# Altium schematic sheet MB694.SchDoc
size A4; Revision: A.1(PCB.SCH)
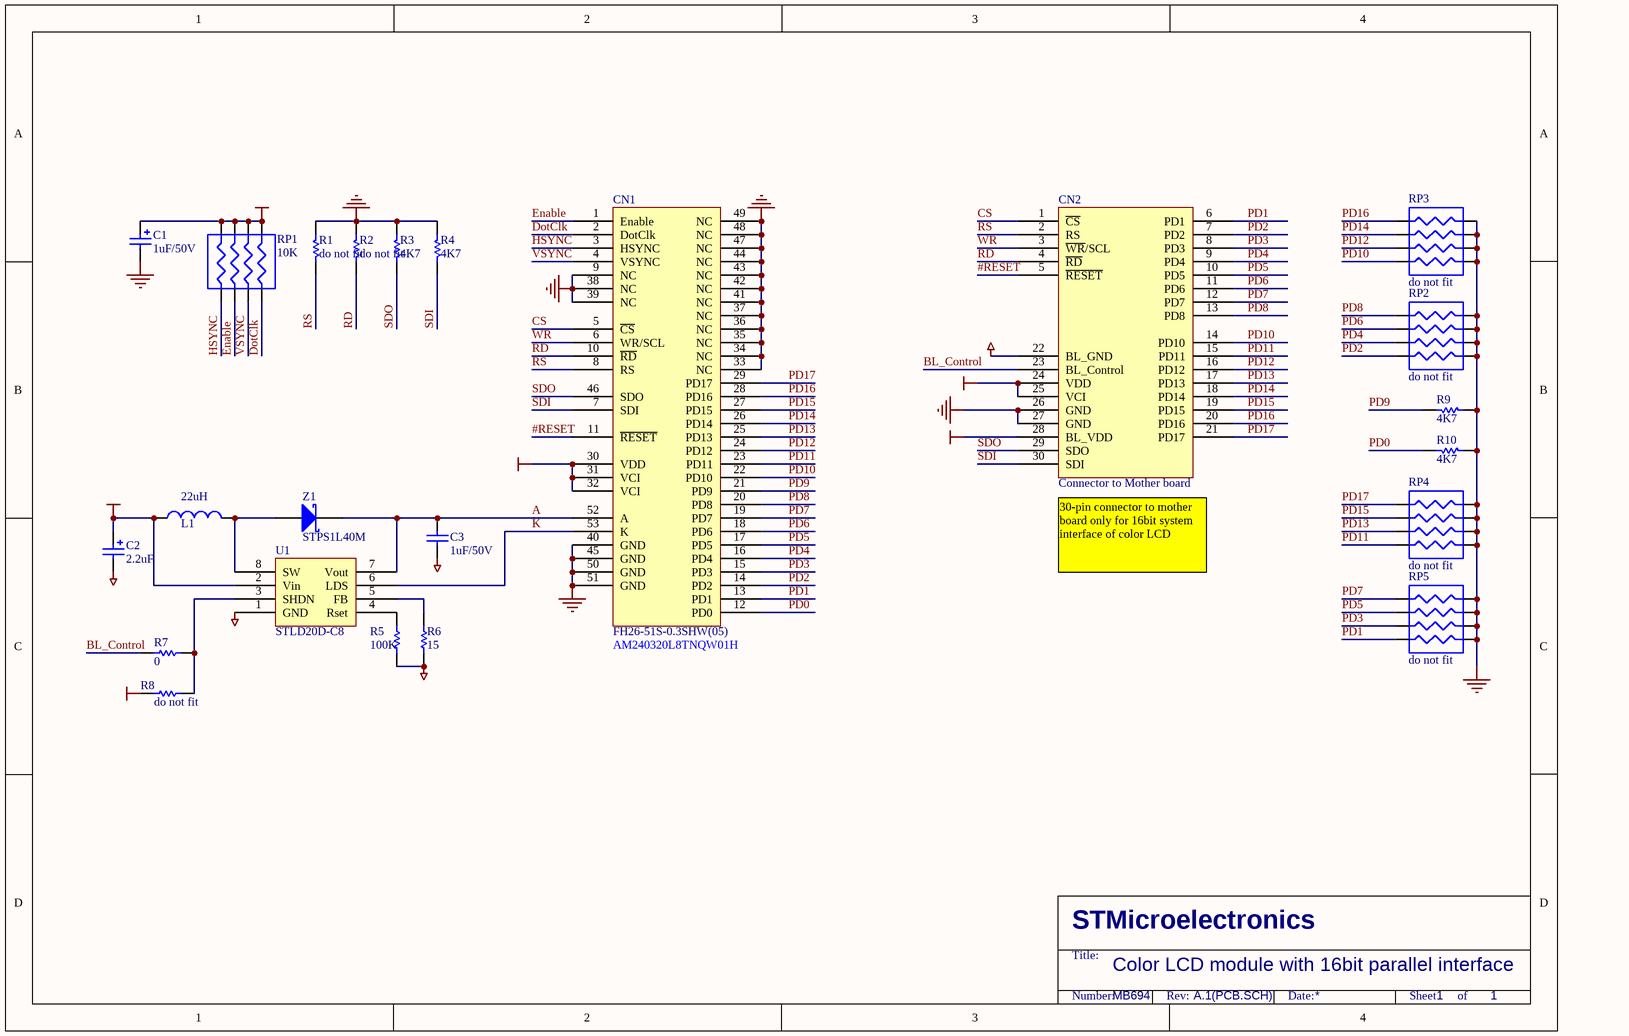
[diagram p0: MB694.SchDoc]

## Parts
C1  1uF/50V  [TAN-B]
C2  2.2uF  [TAN-A]
C3  1uF/50V  [0603]
CN1  FH26-51S-0.3SHW(05)
CN2  Connector to Mother board  [AM240320A]
L1  22uH  [3225]
R1  do not fit  [0603]
R2  do not fit  [0603]
R3  4K7  [0603]
R4  4K7  [0603]
R5  100K  [0603]
R6  15  [0603]
R7  0  [0603]
R8  do not fit  [0603]
R9  4K7  [0603]
R10  4K7  [0603]
RP1  10K  [RES-4B]
RP2  do not fit  [RES-4B]
RP3  do not fit  [RES-4B]
RP4  do not fit  [RES-4B]
RP5  do not fit  [RES-4B]
U1  STLD20D-C8  [SOT23-8L]
Z1  STPS1L40M  [1R1C]

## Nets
BLGND: C2.2 C3.1 CN2.22(BL_GND) R5.1 R6.1 U1.1(GND)
BLVDD: C2.1 CN2.28(BL_VDD) L1.1 R8.2 U1.2(Vin)
GND: C1.2 CN1.9(NC) CN1.33(NC) CN1.34(NC) CN1.35(NC) CN1.36(NC) CN1.37(NC) CN1.38(NC) CN1.39(NC) CN1.40(GND) CN1.41(NC) CN1.42(NC) CN1.43(NC) CN1.44(NC) CN1.45(GND) CN1.47(NC) CN1.48(NC) CN1.49(NC) CN1.50(GND) CN1.51(GND) CN2.26(GND) CN2.27(GND) R1.1 R2.1 R3.1 R4.1 R9.1 R10.1 RP2.2(R1) RP2.4(R3) RP2.6(R2) RP2.8(R0) RP3.2(R1) RP3.4(R3) RP3.6(R2) RP3.8(R0) RP4.2(R1) RP4.4(R3) RP4.6(R2) RP4.8(R0) RP5.2(R1) RP5.4(R3) RP5.6(R2) RP5.8(R0)
VDD: C1.1 CN1.30(VDD) CN1.31(VCI) CN1.32(VCI) CN2.24(VDD) CN2.25(VCI) RP1.2(R1) RP1.4(R3) RP1.6(R2) RP1.8(R0)
#RESET: CN1.11(~{RESET}) CN2.5(~{RESET})
A: C3.2 CN1.52(A) U1.7(Vout) Z1.2(K)
BL_Control: CN2.23(BL_Control) R7.2
CS: CN1.5(~{CS}) CN2.1(~{CS})
DotClk: CN1.2(DotClk) RP1.7(R1)
Enable: CN1.1(Enable) RP1.3(R2)
HSYNC: CN1.3(HSYNC) RP1.1(R0)
K: CN1.53(K) U1.6(LDS)
PD0: CN1.12(PD0) R10.2
PD1: CN1.13(PD1) CN2.6(PD1) RP5.7(R1)
PD2: CN1.14(PD2) CN2.7(PD2) RP2.7(R1)
PD3: CN1.15(PD3) CN2.8(PD3) RP5.5(R3)
PD4: CN1.16(PD4) CN2.9(PD4) RP2.5(R3)
PD5: CN1.17(PD5) CN2.10(PD5) RP5.3(R2)
PD6: CN1.18(PD6) CN2.11(PD6) RP2.3(R2)
PD7: CN1.19(PD7) CN2.12(PD7) RP5.1(R0)
PD8: CN1.20(PD8) CN2.13(PD8) RP2.1(R0)
PD9: CN1.21(PD9) R9.2
PD10: CN1.22(PD10) CN2.14(PD10) RP3.7(R1)
PD11: CN1.23(PD11) CN2.15(PD11) RP4.7(R1)
PD12: CN1.24(PD12) CN2.16(PD12) RP3.5(R3)
PD13: CN1.25(PD13) CN2.17(PD13) RP4.5(R3)
PD14: CN1.26(PD14) CN2.18(PD14) RP3.3(R2)
PD15: CN1.27(PD15) CN2.19(PD15) RP4.3(R2)
PD16: CN1.28(PD16) CN2.20(PD16) RP3.1(R0)
PD17: CN1.29(PD17) CN2.21(PD17) RP4.1(R0)
RD: CN1.10(~{RD}) CN2.4(~{RD}) R2.2
RS: CN1.8(RS) CN2.2(RS) R1.2
SDI: CN1.7(SDI) CN2.30(SDI) R4.2
SDO: CN1.46(SDO) CN2.29(SDO) R3.2
VSYNC: CN1.4(VSYNC) RP1.5(R3)
WR: CN1.6(WR/SCL) CN2.3(~{WR}/SCL)
NetL1_2: L1.2 U1.8(SW) Z1.1(A)
NetR5_2: R5.2 U1.4(Rset)
NetR6_2: R6.2 U1.5(FB)
NetR7_1: R7.1 R8.1 U1.3(SHDN)

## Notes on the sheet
- (near CN2) 30-pin connector to mother board only for 16bit system interface of color LCD
- (near CN1) AM240320L8TNQW01H
- Color LCD module with 16bit parallel interface
- MB694
- 1

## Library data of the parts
C1 C2 = Cap Pol1: Polarized Capacitor (Radial); Value: 100pF
C3 = CAP: Capacitor; Value: 100pF
CN1 = AM240320LTNQW00H
CN2 = ColorLCD_module
L1 = Inductor: Value: 100uH
R1-R10 = Res1: Resistor; Value: 1K
RP1-RP5 = RES4B
Z1 = D Schottky: Schottky Diode; Code - JEDEC: DO-214-AA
